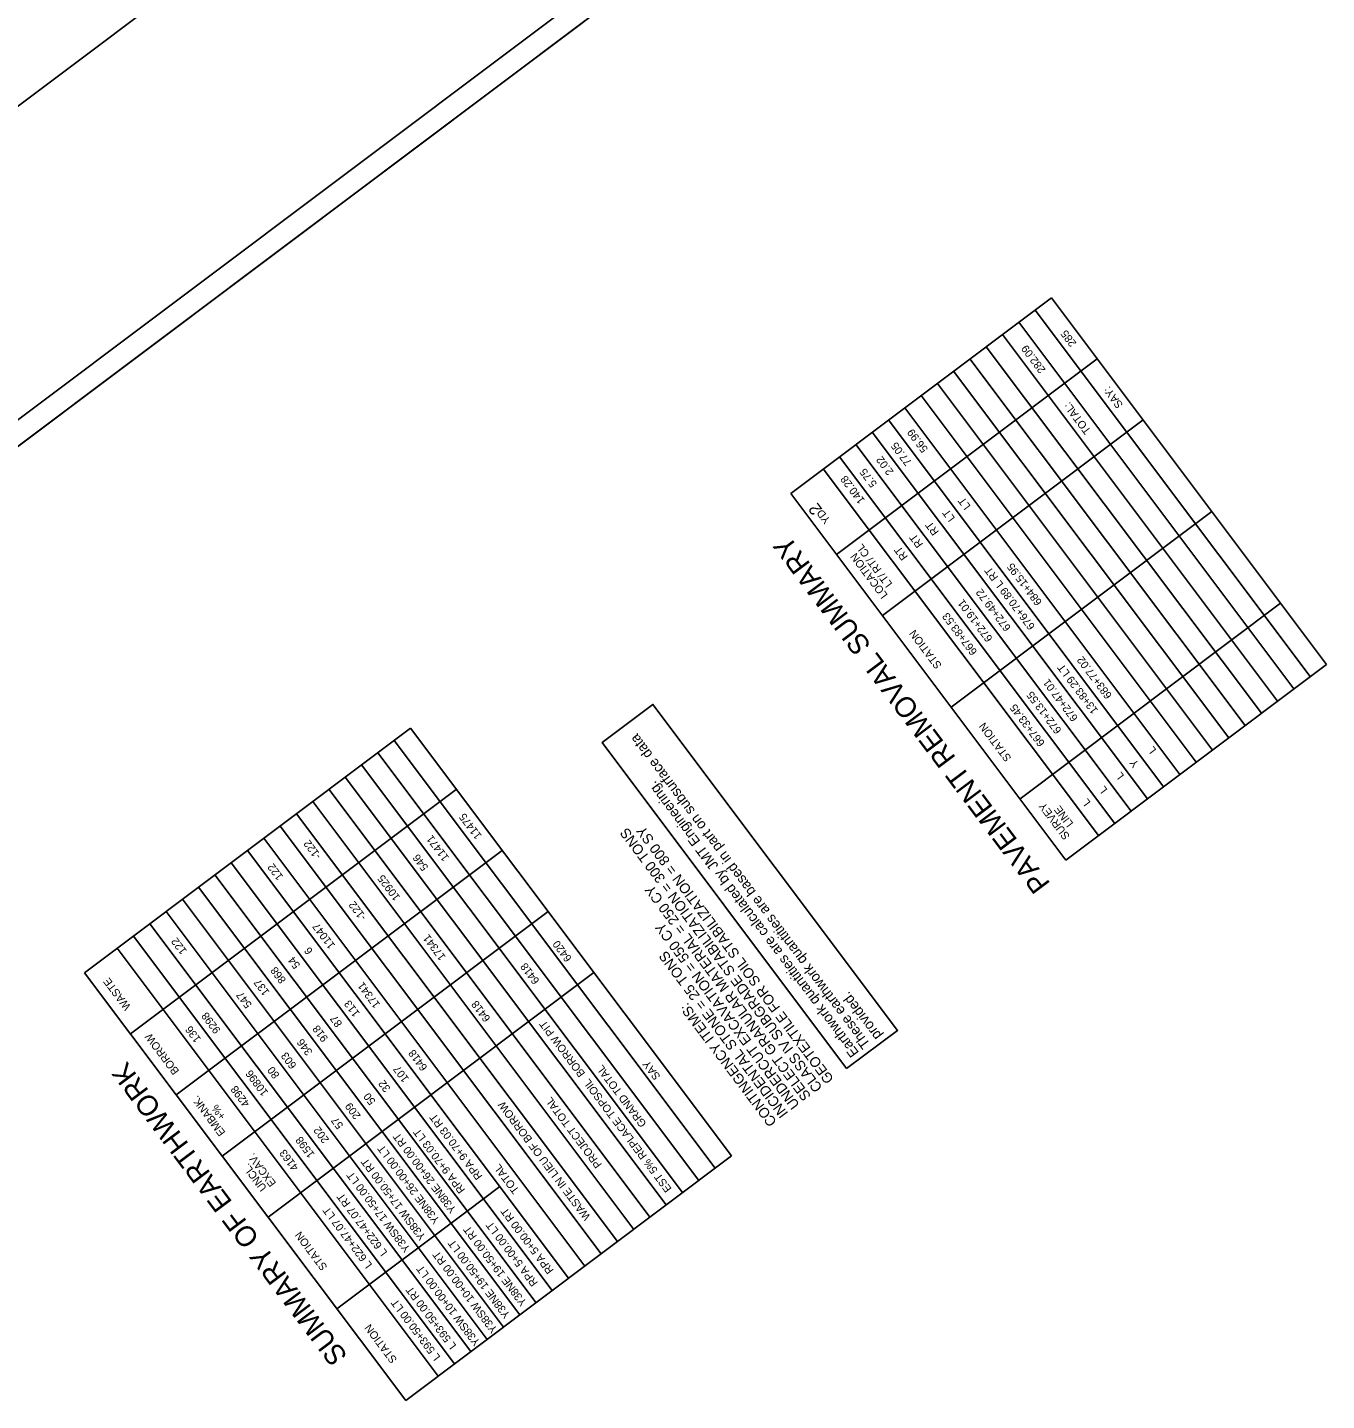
# Model space of a CAD drawing. Extents: x -35.4 to 7.5, y -22.3 to 27.3.
# Drawn here: x -8.42 to 7.53, y -22.29 to -5.44 of the extents above; entities that cross this region are included whole.
import ezdxf

# ---------------------------------------------------------------- set-up
doc = ezdxf.new("R2010")
doc.units = 0
for name, color, linetype in [('Sheet Cutting Line CELL', 7, 'Continuous'), ('Sheet Plot Border Inside CELL', 7, 'Continuous'), ('Sheet Plot Border Outside CELL', 7, 'Continuous'), ('Sheet Summary Combination CELL', 7, 'Continuous'), ('Sheet Summary Combination Grid CELL', 7, 'Continuous'), ('Sheet Summary Earthwork CELL', 7, 'Continuous'), ('Typical Text Asphalt at Bridge Approach CELL', 7, 'Continuous')]:
    doc.layers.add(name, color=color, linetype=linetype)

msp = doc.modelspace()

# ---------------------------------------------------------------- linework, layer by layer
at = {"layer": 'Sheet Cutting Line CELL'}
msp.add_line((-15.19, -15.574), (2.405, -2.368), dxfattribs=at)
at = {"layer": 'Sheet Plot Border Inside CELL'}
msp.add_lwpolyline([(-34.994, 11.561), (-14.987, -15.096), (1.89, -2.429), (-18.117, 24.228)], close=True, dxfattribs=at)
at = {"layer": 'Sheet Plot Border Outside CELL'}
msp.add_lwpolyline([(-35.408, 11.363), (-15.19, -15.574), (2.405, -2.368), (-17.812, 24.569)], close=True, dxfattribs=at)
at = {"layer": 'Sheet Summary Combination CELL'}
for p, q in [((2.383, -13.064), (2.383, -13.064)), ((2.449, -13.155), (2.449, -13.155)), ((2.561, -13.297), (2.561, -13.297)), ((2.634, -13.398), (2.634, -13.398)), ((-5.158, -20.447), (-5.158, -20.447)), ((-5.092, -20.538), (-5.092, -20.538)), ((-4.98, -20.68), (-4.98, -20.68)), ((-4.907, -20.782), (-4.907, -20.782))]:
    msp.add_line(p, q, dxfattribs=at)
msp.add_lwpolyline([(-34.804, 11.392), (-16.795, -12.602), (0, 0.003), (-18.008, 23.997)], close=True, dxfattribs=at)
at = {"layer": 'Sheet Summary Combination Grid CELL'}
for p, q in [((0.951, -11.158), (4.151, -8.757)), ((7.528, -13.257), (4.151, -8.757)), ((7.528, -13.257), (4.151, -8.757)), ((7.328, -13.407), (3.951, -8.907)), ((7.128, -13.557), (3.751, -9.057)), ((6.928, -13.707), (3.551, -9.207)), ((6.928, -13.707), (3.551, -9.207)), ((6.728, -13.857), (3.351, -9.357)), ((1.514, -11.908), (4.714, -9.507)), ((6.528, -14.007), (3.151, -9.507)), ((6.329, -14.158), (2.951, -9.657)), ((6.129, -14.308), (2.751, -9.807)), ((5.729, -14.608), (2.351, -10.107)), ((5.929, -14.458), (2.551, -9.957)), ((2.077, -12.658), (5.277, -10.257)), ((5.529, -14.758), (2.151, -10.257)), ((5.329, -14.908), (1.951, -10.407)), ((5.129, -15.058), (1.751, -10.557)), ((4.929, -15.208), (1.551, -10.708)), ((4.729, -15.358), (1.351, -10.858)), ((4.329, -15.658), (0.951, -11.158)), ((2.921, -13.783), (6.121, -11.382)), ((3.766, -14.908), (6.965, -12.507)), ((4.329, -15.658), (7.528, -13.257)), ((-7.716, -17.041), (-3.717, -14.039)), ((0.224, -19.29), (-3.717, -14.039)), ((0.024, -19.44), (-3.917, -14.19)), ((-0.376, -19.74), (-4.317, -14.49)), ((-0.176, -19.59), (-4.117, -14.34)), ((-0.576, -19.89), (-4.516, -14.64)), ((-7.153, -17.791), (-3.154, -14.79)), ((-0.776, -20.04), (-4.716, -14.79)), ((-0.976, -20.191), (-4.916, -14.94)), ((-1.176, -20.341), (-5.116, -15.09)), ((-1.375, -20.491), (-5.316, -15.24)), ((-1.575, -20.641), (-5.516, -15.39)), ((-6.59, -18.541), (-2.591, -15.54)), ((-1.775, -20.791), (-5.716, -15.54)), ((-1.775, -20.791), (-5.716, -15.54)), ((-2.175, -21.091), (-6.116, -15.84)), ((-1.975, -20.941), (-5.916, -15.69)), ((-2.375, -21.241), (-6.316, -15.99)), ((-2.575, -21.391), (-6.516, -16.14)), ((-2.775, -21.541), (-6.716, -16.29)), ((-6.026, -19.291), (-2.027, -16.29)), ((-2.975, -21.691), (-6.916, -16.441)), ((-3.175, -21.841), (-7.116, -16.591)), ((-3.375, -21.991), (-7.316, -16.741)), ((-3.775, -22.291), (-7.716, -17.041)), ((-5.463, -20.042), (-1.464, -17.04)), ((-3.775, -22.291), (0.224, -19.29)), ((-3.02, -19.966), (-2.62, -19.665)), ((-4.619, -21.166), (-3.02, -19.966))]:
    msp.add_line(p, q, dxfattribs=at)
at = {"layer": 'Sheet Summary Earthwork CELL'}
msp.add_lwpolyline([(1.638, -18.217), (-1.364, -14.217), (-0.74, -13.748), (2.262, -17.748)], close=True, dxfattribs=at)
at = {"layer": 'Typical Text Asphalt at Bridge Approach CELL'}
for p, q in [((0.224, -19.29), (-3.717, -14.039)), ((0.024, -19.44), (-3.917, -14.19)), ((-0.376, -19.74), (-4.317, -14.49)), ((-0.176, -19.59), (-4.117, -14.34))]:
    msp.add_line(p, q, dxfattribs=at)

# ---------------------------------------------------------------- texts
at = {"layer": 'Sheet Summary Combination CELL'}
for s, height, rotation, p in [('285', 0.096, 126.8893, (4.463, -9.314)), ('282.09', 0.096, 126.8893, (4.085, -9.64)), ('SAY:', 0.096, 126.8893, (5.035, -10.069)), ('TOTAL:', 0.096, 126.8893, (4.642, -10.388)), ('56.99', 0.096, 126.8893, (2.642, -10.613)), ('77.05', 0.096, 126.8893, (2.442, -10.775)), ('2.02', 0.096, 126.8893, (2.219, -10.89)), ('140.28', 0.096, 126.8893, (1.866, -11.242)), ('5.75', 0.096, 126.8893, (2.016, -11.04)), ('LT', 0.096, 126.8893, (3.165, -11.314)), ('LT', 0.096, 126.8893, (2.973, -11.461)), ('RT', 0.096, 126.8893, (2.776, -11.629)), ('PAVEMENT REMOVAL SUMMARY', 0.25, 126.9013, (4.145, -15.948)), ('LT/ RT/ CL', 0.096, 126.8893, (2.203, -12.268)), ('RT', 0.096, 126.8893, (2.581, -11.781)), ('LOCATION', 0.096, 126.8893, (2.147, -12.404)), ('RT', 0.096, 126.8893, (2.394, -11.935)), ('676+70.89 L RT', 0.096, 126.8893, (3.955, -12.789)), ('684+15.95', 0.096, 126.8893, (4.041, -12.491)), ('672+19.01', 0.096, 126.8893, (3.435, -12.937)), ('672+49.72', 0.096, 126.8893, (3.659, -12.806)), ('667+83.53', 0.096, 126.8893, (3.246, -13.1)), ('STATION', 0.096, 126.8893, (2.81, -13.267)), ('13+83.29 LT', 0.096, 126.8893, (4.729, -13.82)), ('683+77.02', 0.096, 126.8893, (4.9, -13.636)), ('672+47.01', 0.096, 126.8893, (4.483, -13.913)), ('672+13.55', 0.096, 126.8893, (4.281, -14.065)), ('667+33.45', 0.096, 126.8893, (4.076, -14.221)), ('STATION', 0.096, 126.8893, (3.665, -14.405)), ('L', 0.096, 126.8893, (5.444, -14.308)), ('Y', 0.096, 126.8893, (5.231, -14.479)), ('L', 0.096, 126.8893, (5.049, -14.624)), ('L', 0.096, 126.8893, (4.844, -14.796)), ('SURVEY', 0.096, 126.8893, (4.383, -15.364)), ('LINE', 0.096, 126.8893, (4.425, -15.21)), ('L', 0.096, 126.8893, (4.637, -14.952)), ('11475', 0.096, 126.8893, (-2.836, -15.359)), ('-122', 0.096, 126.8893, (-4.805, -15.606)), ('11471', 0.096, 126.8893, (-3.237, -15.628)), ('546', 0.096, 126.8893, (-3.491, -15.746)), ('122', 0.096, 126.8893, (-5.273, -15.861)), ('10925', 0.096, 126.8893, (-3.837, -16.114)), ('-122', 0.096, 126.8893, (-4.251, -16.358)), ('11047', 0.096, 126.8893, (-4.636, -16.705)), ('122', 0.096, 126.8893, (-6.456, -16.772)), ('17341', 0.096, 126.8893, (-3.279, -16.846)), ('6420', 0.096, 126.8893, (-1.731, -16.863)), ('54', 0.096, 126.8893, (-5.064, -16.948)), ('6', 0.096, 126.8893, (-4.909, -16.773)), ('868', 0.096, 126.8893, (-5.238, -17.129)), ('6418', 0.096, 126.8893, (-2.127, -17.138)), ('WASTE', 0.096, 126.8893, (-7.143, -17.457)), ('137', 0.096, 126.8893, (-5.442, -17.278)), ('17341', 0.096, 126.8893, (-4.083, -17.431)), ('547', 0.096, 126.8893, (-5.657, -17.432)), ('113', 0.096, 126.8893, (-4.333, -17.539)), ('6418', 0.096, 126.8893, (-2.729, -17.601)), ('9298', 0.096, 126.8893, (-6.042, -17.744)), ('918', 0.096, 126.8893, (-4.721, -17.846)), ('87', 0.096, 126.8893, (-4.548, -17.665)), ('EST 5% REPLACE TOPSOIL  BORROW PIT', 0.096, 126.8893, (-0.505, -19.692)), ('BORROW', 0.096, 126.8893, (-6.55, -18.247)), ('136', 0.096, 126.8893, (-6.283, -17.854)), ('346', 0.096, 126.8893, (-4.913, -18.012)), ('603', 0.096, 126.8893, (-5.108, -18.177)), ('6418', 0.096, 126.8893, (-3.502, -18.202)), ('SUMMARY OF EARTHWORK', 0.25, 126.9013, (-4.479, -21.743)), ('80', 0.096, 126.8893, (-5.318, -18.296)), ('107', 0.096, 126.8893, (-3.73, -18.341)), ('GRAND TOTAL', 0.096, 126.8893, (-0.814, -18.893)), ('SAY', 0.096, 126.8893, (-0.643, -18.313)), ('10896', 0.096, 126.8893, (-5.457, -18.51)), ('32', 0.096, 126.8893, (-3.956, -18.461)), ('4298', 0.096, 126.8893, (-5.683, -18.645)), ('50', 0.096, 126.8893, (-4.139, -18.619)), ('EMBANK.', 0.096, 126.8893, (-5.983, -19.002)), ('+%', 0.096, 126.8893, (-5.977, -18.8)), ('209', 0.096, 126.8893, (-4.322, -18.796)), ('WASTE IN LIEU OF BORROW', 0.096, 126.8893, (-1.501, -20.035)), ('PROJECT TOTAL', 0.096, 126.8893, (-1.362, -19.395)), ('57', 0.096, 126.8893, (-4.535, -18.915)), ('RPA 9+70.03 RT', 0.096, 126.8893, (-2.828, -19.538)), ('202', 0.096, 126.8893, (-4.709, -19.09)), ('Y38NE 26+00.00 RT', 0.096, 126.8893, (-3.148, -19.946)), ('RPA 9+70.03 LT', 0.096, 126.8893, (-3.04, -19.705)), ('1598', 0.096, 126.8893, (-4.887, -19.269)), ('Y38NE 26+00.00 LT', 0.096, 126.8893, (-3.351, -20.077)), ('EXCAV.', 0.096, 126.8893, (-5.36, -19.623)), ('4163', 0.096, 126.8893, (-5.085, -19.428)), ('Y38SW 17+50.00 RT', 0.096, 126.8893, (-3.523, -20.28)), ('UNCL.', 0.096, 126.8893, (-5.475, -19.68)), ('Y38SW 17+50.00 LT', 0.096, 126.8893, (-3.712, -20.427)), ('TOTAL', 0.096, 126.8893, (-2.376, -19.709)), ('L 622+47.07 RT', 0.096, 126.8893, (-3.995, -20.474)), ('L 622+47.07 LT', 0.096, 126.8893, (-4.181, -20.625)), ('RPA 5+00.00 RT', 0.096, 126.8893, (-1.954, -20.693)), ('STATION', 0.096, 126.8893, (-4.731, -20.651)), ('Y38NE 19+50.00 RT', 0.096, 126.8893, (-2.284, -21.087)), ('RPA 5+00.00 LT', 0.096, 126.8893, (-2.148, -20.846)), ('Y38NE 19+50.00 LT', 0.096, 126.8893, (-2.486, -21.239)), ('Y38SW 10+00.00 RT', 0.096, 126.8893, (-2.644, -21.419)), ('Y38SW 10+00.00 LT', 0.096, 126.8893, (-2.856, -21.576)), ('L 593+50.00 LT', 0.096, 126.8893, (-3.344, -21.758)), ('L 593+50.00 RT', 0.096, 126.8893, (-3.148, -21.618)), ('STATION', 0.096, 126.8893, (-3.876, -21.789))]:
    msp.add_text(s, height=height, rotation=rotation, dxfattribs=at).set_placement(p)
at = {"layer": 'Sheet Summary Combination Grid CELL'}
for s, height, p in [('2', 0.15, (1.344, -11.352)), ('YD', 0.096, (1.445, -11.486))]:
    msp.add_text(s, height=height, rotation=126.8893, dxfattribs=at).set_placement(p)
at = {"layer": 'Sheet Summary Earthwork CELL'}
for s, p in [('These earthwork quantities are based in part on subsurface data ', (1.934, -17.916)), ('Earthwork quantities are calculated by JMT Engineering.', (1.794, -18.021)), ('CLASS IV SUBGRADE STABILIZATION = 300 TONS', (1.346, -18.449)), ('GEOTEXTILE FOR SOIL STABILIZATION = 800 SY', (1.486, -18.344)), ('SELECT GRANULAR MATERIAL = 250 CY', (1.206, -18.554)), ('UNDERCUT EXCAVATION = 550 CY', (1.066, -18.66)), ('INCIDENTAL STONE = 25 TONS', (0.926, -18.765)), ('provided.', (2.074, -17.811)), ('CONTINGENCY ITEMS:', (0.786, -18.87))]:
    msp.add_text(s, height=0.125, rotation=126.8893, dxfattribs=at).set_placement(p)

doc.saveas('drawing.dxf')
